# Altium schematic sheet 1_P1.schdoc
size 431 x 309 mm; Symbol: Sheet-Symbol_A4; Device: Sheet-Symbol_A4; Company: 嘉立创EDA; Version: V1.0; Page Size: A4; @Project Name: PiezoBuds-final; @Page Count: 1; @Update Date: 2024-03-19; @Create Date: 2024-03-19; @Schematic Name: Schematic1; @Page No: 1; @Page Name: P1
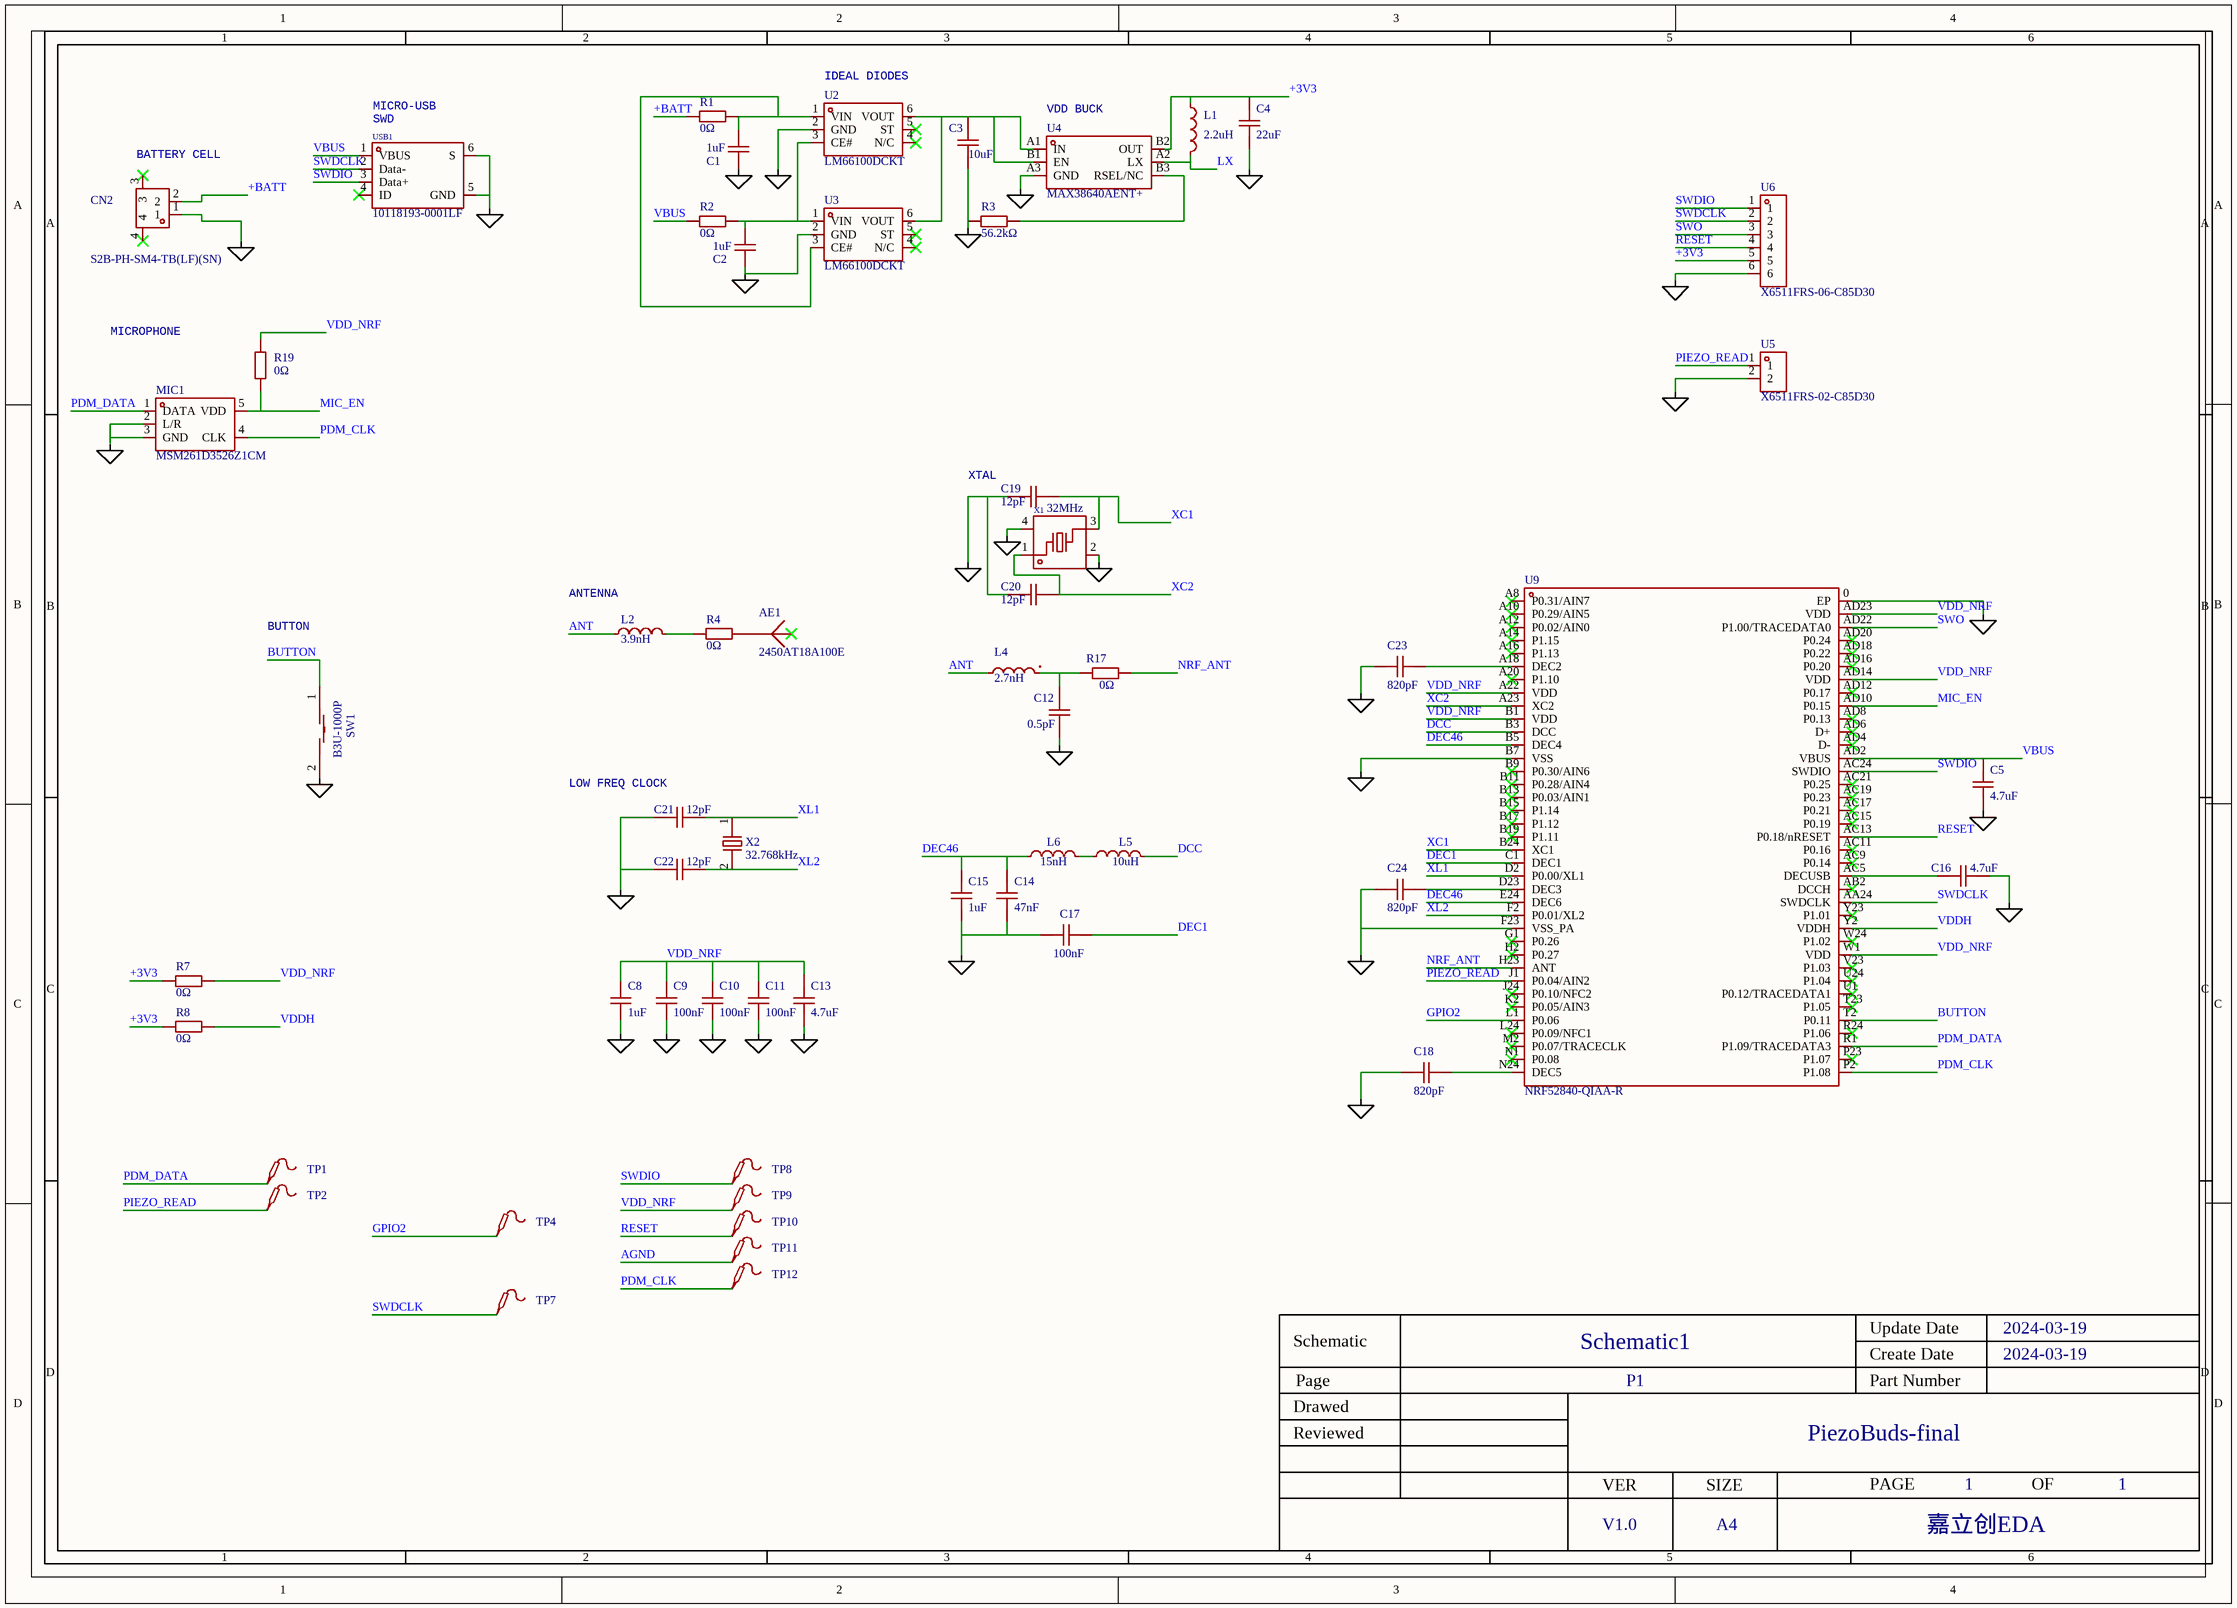
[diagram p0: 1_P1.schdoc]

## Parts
AE1  2450AT18A100E  [ANT-SMD_L3.2-W1.6]  (value not drawn)
C1  1uF  [C0402]  (value not drawn)
C2  1uF  [C0402]  (value not drawn)
C3  10uF  [C0402]  (value not drawn)
C4  22uF  [C0402]  (value not drawn)
C5  4.7uF  [C0402]  (value not drawn)
C8  1uF  [C0402]  (value not drawn)
C9  100nF  [C0201]  (value not drawn)
C10  100nF  [C0201]  (value not drawn)
C11  100nF  [C0201]  (value not drawn)
C12  0.5pF  [C0201]  (value not drawn)
C13  4.7uF  [C0402]  (value not drawn)
C14  47nF  [C0201]  (value not drawn)
C15  1uF  [C0402]  (value not drawn)
C16  4.7uF  [C0402]  (value not drawn)
C17  100nF  [C0201]  (value not drawn)
C18  820pF  [C0201]  (value not drawn)
C19  12pF  [C0201]  (value not drawn)
C20  12pF  [C0201]  (value not drawn)
C21  12pF  [C0201]  (value not drawn)
C22  12pF  [C0201]  (value not drawn)
C23  820pF  [C0201]  (value not drawn)
C24  820pF  [C0201]  (value not drawn)
CN2  S2B-PH-SM4-TB(LF)(SN)  [CONN-SMD_P2.00_S2B-PH-SM4-TB-LF-SN]  (value not drawn)
L1  2.2uH  [L0603]  (value not drawn)
L2  3.9nH  [IND-SMD_L1.0-W0.5-2]  (value not drawn)
L4  2.7nH  [L0201-RD]  (value not drawn)
L5  10uH  [L0603]  (value not drawn)
L6  15nH  [L0201]  (value not drawn)
MIC1  MSM261D3526Z1CM  [OCLGA-6_L3.5-W2.7-TL-MSM261D3526Z1CM]  (value not drawn)
R1  0Ω  [R0201]  (value not drawn)
R2  0Ω  [R0201]  (value not drawn)
R3  56.2kΩ  [R0201]  (value not drawn)
R4  0Ω  [R0201]  (value not drawn)
R7  0Ω  [R0402]  (value not drawn)
R8  0Ω  [R0402]  (value not drawn)
R17  0Ω  [R0201]  (value not drawn)
R19  0Ω  [R0201]  (value not drawn)
SW1  B3U-1000P  [KEY-SMD_B3U-1000PM]  (value not drawn)
TP1  Test-Point  [Test-Point-0.5mm]  (value not drawn)
TP2  Test-Point  [Test-Point-0.5mm]  (value not drawn)
TP4  Test-Point  [Test-Point-0.5mm]  (value not drawn)
TP7  Test-Point  [Test-Point-0.5mm]  (value not drawn)
TP8  Test-Point  [Test-Point-0.5mm]  (value not drawn)
TP9  Test-Point  [Test-Point-0.5mm]  (value not drawn)
TP10  Test-Point  [Test-Point-0.5mm]  (value not drawn)
TP11  Test-Point  [Test-Point-0.5mm]  (value not drawn)
TP12  Test-Point  [Test-Point-0.5mm]  (value not drawn)
U2  LM66100DCKT  [SC-70-6_L2.0-W1.3-P0.65-LS2.1-BL]  (value not drawn)
U3  LM66100DCKT  [SC-70-6_L2.0-W1.3-P0.65-LS2.1-BL]  (value not drawn)
U4  MAX38640AENT+  [WLP-6_L1.4-W0.9-R2-C3-P0.40-TL]  (value not drawn)
U5  X6511FRS-02-C85D30  [HDR-SMD_2P-P2.54-H-F-L11.5]  (value not drawn)
U6  X6511FRS-06-C85D30  [HDR-SMD_6P-P2.54-H-F-L11.5]  (value not drawn)
U9  NRF52840-QIAA-R  [AQFN-73_L7.0-W7.0-P0.50-BL-EP4.8]  (value not drawn)
USB1  10118193-0001LF  [MICRO-USB-SMD_10118193-0001LF]  (value not drawn)
X1  32MHz  [CRYSTAL-SMD_4P-L2.0-W1.6-BL]  (value not drawn)
X2  32.768kHz  [CRYSTAL-SMD_L3.2-W1.5-1]  (value not drawn)

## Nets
AGND: C1.1 C2.1 C3.1 C4.1 C5.2 C8.1 C9.2 C10.2 C11.2 C12.1 C13.1 C14.2 C15.1 C16.1 C17.2 C18.1 C19.1 C20.1 C21.1 C22.1 C23.1 C24.1 CN2.1 MIC1.2(L/R) MIC1.3(GND) R3.1 SW1.2 TP11.1 U2.2(GND) U3.2(GND) U4.A3(GND) U5.2 U6.6 U9.0(EP) U9.B7(VSS) U9.F23(VSS_PA) USB1.5(GND) USB1.6(S) X1.2(GND) X1.4(GND)
+3V3: C4.2 L1.1 R7.1 R8.1 U4.B2(OUT) U6.5
+BATT: CN2.2 R1.1
ANT: L2.1 L4.2
BUTTON: SW1.1 U9.T2(P0.11)
DCC: L5.2 U9.B3(DCC)
DEC1: C17.1 U9.C1(DEC1)
DEC46: C14.1 C15.2 L6.1 U9.B5(DEC4) U9.E24(DEC6)
GPIO2: TP4.1 U9.L1(P0.06)
LX: L1.2 U4.A2(LX)
MIC_EN: MIC1.5(VDD) R19.1 U9.AD10(P0.15)
NRF_ANT: R17.2 U9.H23(ANT)
PDM_CLK: MIC1.4(CLK) TP12.1 U9.P2(P1.08)
PDM_DATA: MIC1.1(DATA) TP1.1 U9.R1(P1.09/TRACEDATA3)
PIEZO_READ: TP2.1 U5.1 U9.J1(P0.04/AIN2)
RESET: TP10.1 U6.4 U9.AC13(P0.18/nRESET)
SWDCLK: TP7.1 U6.2 U9.AA24(SWDCLK) USB1.2(Data-)
SWDIO: TP8.1 U6.1 U9.AC24(SWDIO) USB1.3(Data+)
SWO: U6.3 U9.AD22(P1.00/TRACEDATA0)
VBUS: C5.1 R2.1 U9.AD2(VBUS) USB1.1(VBUS)
VDD_NRF: C8.2 C9.1 C10.1 C11.1 C13.2 R7.2 R19.2 TP9.1 U9.A22(VDD) U9.AD14(VDD) U9.AD23(VDD) U9.B1(VDD) U9.W1(VDD)
VDDH: R8.2 U9.Y2(VDDH)
XC1: C19.2 U9.B24(XC1) X1.3
XC2: C20.2 U9.A23(XC2) X1.1
XL1: C21.2 U9.D2(P0.00/XL1) X2.1
XL2: C22.2 U9.F2(P0.01/XL2) X2.2
NetAE1_1: AE1.1(ANT) R4.2
NetC1_2: C1.2 R1.2 U2.1(VIN) U3.3(CE#)
NetC2_2: C2.2 R2.2 U2.3(CE#) U3.1(VIN)
NetC3_2: C3.2 U2.6(VOUT) U3.6(VOUT) U4.A1(IN) U4.B1(EN)
NetC12_2: C12.2 L4.1 R17.1
NetC16_2: C16.2 U9.AC5(DECUSB)
NetC18_2: C18.2 U9.N24(DEC5)
NetC23_2: C23.2 U9.A18(DEC2)
NetC24_2: C24.2 U9.D23(DEC3)
NetL2_2: L2.2 R4.1
NetL5_1: L5.1 L6.2
NetR3_2: R3.2 U4.B3(RSEL/NC)

Not connected (* = marked no-connect by the designer): AE1 2*; CN2 3* 4*; U2 4(N/C)* 5(ST)*; U3 4(N/C)* 5(ST)*; U9 A8(P0.31/AIN7)* A10(P0.29/AIN5)* A12(P0.02/AIN0)* A14(P1.15)* A16(P1.13)* A20(P1.10)* AB2(DCCH)* AC9(P0.14)* AC11(P0.16)* AC15(P0.19)* AC17(P0.21)* AC19(P0.23)* AC21(P0.25)* AD4(D-)* AD6(D+)* AD8(P0.13)* AD12(P0.17)* AD16(P0.20)* AD18(P0.22)* AD20(P0.24)* B9(P0.30/AIN6)* B11(P0.28/AIN4)* B13(P0.03/AIN1)* B15(P1.14)* B17(P1.12)* B19(P1.11)* G1(P0.26)* H2(P0.27)* J24(P0.10/NFC2)* K2(P0.05/AIN3)* L24(P0.09/NFC1)* M2(P0.07/TRACECLK)* N1(P0.08)* P23(P1.07)* R24(P1.06)* T23(P1.05)* U1(P0.12/TRACEDATA1)* U24(P1.04)* V23(P1.03)* W24(P1.02)* Y23(P1.01)*; USB1 4(ID)*

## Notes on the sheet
- (near USB1) MICRO-USB
  SWD
- (near U2) IDEAL DIODES
- (near U4) VDD BUCK
- (near CN2) BATTERY CELL
- MICROPHONE
- (near C19) XTAL
- BUTTON
- (near L2) ANTENNA
- (near C21) LOW FREQ CLOCK

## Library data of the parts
AE1 = 2450AT18A100E: 天线类型:迷你2.45 GHz天线;中心频点:2.4GHz;带宽:-;峰值增益:0.5dBi;驻波比:-;极化方式:-;阻抗:50Ω;功率容量:2W;; Manufacturer: JOHANSON(约翰逊); Add into BOM: yes; Central Frequency: 2.4GHz; Peak Gain: 0.5dBi; Impedance: 50Ω; Power capacity: 2W
C1 C2 C8 = CL05A105KQ5NNNC: 容值:1uF;精度:±10%;额定电压:6.3V;材质(温度系数):X5R;; Manufacturer: SAMSUNG(三星); Add into BOM: yes; Tolerance: ±10%; Voltage Rated: 6.3V; Temperature Coefficient: X5R
C3 = CL05A106MP5NUNC: 容值:10uF;精度:±20%;额定电压:10V;材质(温度系数):X5R;; Manufacturer: SAMSUNG(三星); Symbol: CL05A106MP5NUNC_C315248; Add into BOM: yes; Tolerance: ±20%; Voltage Rated: 10V; Temperature Coefficient: X5R
C4 = GRM155R60J226ME11D: 容值:22uF;精度:±20%;额定电压:6.3V;材质(温度系数):X5R;; Manufacturer: muRata(村田); Add into BOM: yes; Tolerance: ±20%; Voltage Rated: 6.3V; Temperature Coefficient: X5R
C5 = C1005X6S0G475M050BC: 容值:4.7uF;精度:±20%;额定电压:4V;材质(温度系数):X6S;; Manufacturer: TDK; Add into BOM: yes; Tolerance: ±20%; Voltage Rated: 4V; Temperature Coefficient: X6S
C9-C11 = GRM033C71C104KE14D: 容值:100nF;精度:±10%;额定电压:16V;材质(温度系数):X7S;; Manufacturer: muRata(村田); Add into BOM: yes; Tolerance: ±10%; Voltage Rated: 16V; Temperature Coefficient: X7S
C12 = 0201CG0R5B250NT: 容值:0.5pF;额定电压:25V;材质(温度系数):C0G;; Manufacturer: FH(风华); Add into BOM: yes; Voltage Rated: 25V; Temperature Coefficient: C0G
C13 C16 = CL05A475KP5NRNC: 容值:4.7uF;精度:±10%;额定电压:10V;材质(温度系数):X5R;; Manufacturer: SAMSUNG(三星); Add into BOM: yes; Tolerance: ±10%; Voltage Rated: 10V; Temperature Coefficient: X5R
C14 = CL03A473KQ3NNNC: 容值:47nF;精度:±10%;额定电压:6.3V;材质(温度系数):X5R;; Manufacturer: SAMSUNG(三星); Add into BOM: yes; Tolerance: ±10%; Voltage Rated: 6.3V; Temperature Coefficient: X5R
C15 = GRM155R70J105KA12D: 容值:1uF;精度:±10%;额定电压:6.3V;材质(温度系数):X7R;; Manufacturer: muRata(村田); Add into BOM: yes; Tolerance: ±10%; Voltage Rated: 6.3V; Temperature Coefficient: X7R
C17 = CL03A104KQ3NNNC: 容值:100nF;精度:±10%;额定电压:6.3V;材质(温度系数):X5R;; Manufacturer: SAMSUNG(三星); Add into BOM: yes; Tolerance: ±10%; Voltage Rated: 6.3V; Temperature Coefficient: X5R
C18 C23 C24 = GRM0335C1E821JA01D: 容值:820pF;精度:±5%;额定电压:25V;材质(温度系数):C0G;; Manufacturer: muRata(村田); Add into BOM: yes; Tolerance: ±5%; Voltage Rated: 25V; Temperature Coefficient: C0G
C19-C22 = GRM0335C1E120GA01D: 容值:12pF;精度:±2%;额定电压:25V;材质(温度系数):C0G;; Manufacturer: muRata(村田); Add into BOM: yes; Tolerance: ±2%; Voltage Rated: 25V; Temperature Coefficient: C0G
CN2 = S2B-PH-SM4-TB(LF)(SN): 插针结构:1x2P;间距:2mm;安装方式:卧贴;参考系列:PH;总PIN数:2P;排数:1;每排PIN数:2;行距:-;额定电流:2A;触头材质:铜合金;触头镀层:锡;工作温度范围:-25℃~+85℃;; Manufacturer: JST; Add into BOM: yes; Pins Structure: 1x2P; Pitch: 2mm; Reference Series: PH; Number of PINs Per Row: 2; Current Rating (Max): 2A
L1 = SLM16082R2MIT: 类型:-;电感值:2.2uH;精度:±20%;额定电流:250mA;饱和电流(Isat):-;; Manufacturer: Sunltech(韩国顺磁); Add into BOM: yes; Tolerance: ±20%; Rated Current: 250mA; DC Resistance (DCR): 520mΩ
L2 = LQW15AN3N9C00D: 电感值:3.9nH;额定电流:-;饱和电流(Isat):-;直流电阻(DCR):70mΩ;; Manufacturer: muRata(村田); Add into BOM: yes; DC Resistance (DCR): 70mΩ; Q @ Freq: 25@250MHz; Frequency - Self Resonant: 10GHz
L4 = LQP03TG2N7B02D: 电感值:2.7nH;精度:-;额定电流:450mA;饱和电流(Isat):-;直流电阻(DCR):250mΩ;; Manufacturer: muRata(村田); Add into BOM: yes; Rated Current: 450mA; DC Resistance (DCR): 250mΩ; Q @ Freq: 13@500MHz; Frequency - Self Resonant: 13.1GHz
L5 = MLZ1608N100LT000: 电感值:10uH;精度:±20%;额定电流:300mA;饱和电流(Isat):60mA;直流电阻(DCR):600mΩ;; Manufacturer: TDK; Add into BOM: yes; Tolerance: ±20%; Rated Current: 300mA; Saturation Current (Isat): 60mA; DC Resistance (DCR): 600mΩ
L6 = LQP03TN15NJ02D: 直流电阻(DCR):700mΩ;精度:±5%;电感值:15nH;额定电流:3.8A;饱和电流(Isat):-;; Manufacturer: muRata(村田); Add into BOM: yes; DC Resistance (DCR): 700mΩ; Tolerance: ±5%; Rated Current: 3.8A; Q @ Freq: 12 500MHz; Frequency - Self Resonant: 2.6GHz
MIC1 = MSM261D3526Z1CM: 方向:全指向;灵敏度:-26dB；-25dB;信噪比:62dB；64dB;电流消耗:670uA；290uA;电源电压:1.8V;阻抗:-;; Manufacturer: MEMS(敏芯微); Add into BOM: yes; Direction: 全指向; Supply Voltage: 1.8V
R1 R2 R4 R17 R19 = RC0201JR-070RL: 温度系数:-;工作温度范围:-55℃~+155℃;电阻长:-;精度:±5%;电阻直径:-;电阻高:-;电阻宽:-;最大工作电压:25V;电阻类型:厚膜电阻;阻值:0Ω;功率:50mW;; Manufacturer: YAGEO(国巨); Add into BOM: yes; Tolerance: ±5%; Overload Voltage (Max): 25V; Power(Watts): 50mW
R3 = RC0201FR-0756K2L: 电阻类型:厚膜电阻;阻值:56.2kΩ;精度:±1%;功率:50mW;最大工作电压:25V;温度系数:±200ppm/℃;; Manufacturer: YAGEO(国巨); Symbol: 0201WMF7683TCE; Add into BOM: yes; Tolerance: ±1%; Power(Watts): 50mW; Overload Voltage (Max): 25V
R7 R8 = RC0402FR-070RL: 电阻类型:厚膜电阻;阻值:0Ω;精度:-;功率:62.5mW;; Manufacturer: YAGEO(国巨); Add into BOM: yes; Power(Watts): 62.5mW; Overload Voltage (Max): 50V
SW1 = B3U-1000P: 触点电流:50mA;额定电压(DC):12V;电路结构:单刀单掷;安装方式:立贴;带灯:-;机械寿命:-;; Manufacturer: OMRON(欧姆龙); Add into BOM: yes; Contact Current: 50mA; Voltage Rating (DC): 12V; Circuit: 单刀单掷; Actuator Style: 圆形按钮; Switch Length: 3mm; Switch Width: 2.5mm; Switch Height: 1.6mm
TP1 TP2 TP4 TP7-TP12 = Test-Point: Test Point 测试点; Add into BOM: yes
U2 U3 = LM66100DCKT_C2832141: Manufacturer: TI(德州仪器); Add into BOM: yes
U4 = MAX38640AENT+: Manufacturer: ADI(亚德诺); Add into BOM: yes
U5 = X6511FRS-02-C85D30: 插孔结构:1x2P;间距:2.54mm;安装类型:卧贴;排数:单排;总孔位数:2P;塑高:8.5mm;; Manufacturer: XKB Connectivity(中国星坤); Add into BOM: yes; Holes Structure: 1x2P; Pitch: 2.54mm; Number of Holes: 2P
U6 = X6511FRS-06-C85D30: 插孔结构:1x6P;间距:2.54mm;安装类型:卧贴;排数:单排;总孔位数:6P;塑高:8.5mm;; Manufacturer: XKB Connectivity(中国星坤); Add into BOM: yes; Holes Structure: 1x6P; Pitch: 2.54mm; Number of Holes: 6P
U9 = NRF52840-QIAA-R: Manufacturer: NORDIC; Add into BOM: yes
USB1 = 10118193-0001LF: Manufacturer: Amphenol; Add into BOM: yes
X1 = Q22FA1280002500: 晶振类型:贴片晶振;频率:32MHz;常温频差:±10ppm;外接负载电容:8pF;; Manufacturer: EPSON(爱普生); Add into BOM: yes; Crystal Type: 贴片晶振; Frequency Tolerance: ±10ppm; Load Capacitance: 8pF; Equivalent Series Resistance (ESR): 60Ω
X2 = NX3215SA-32.768K-STD-MUA-9: 晶振类型:-;频率:32.768kHz;常温频差:±20ppm;外接负载电容:9pF;; Manufacturer: NDK; Add into BOM: yes; Normal temperature Frequency Tolerance: ±20ppm; External load capacitor: 9pF; Equivalent Series Resistance (ESR): 70kΩ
